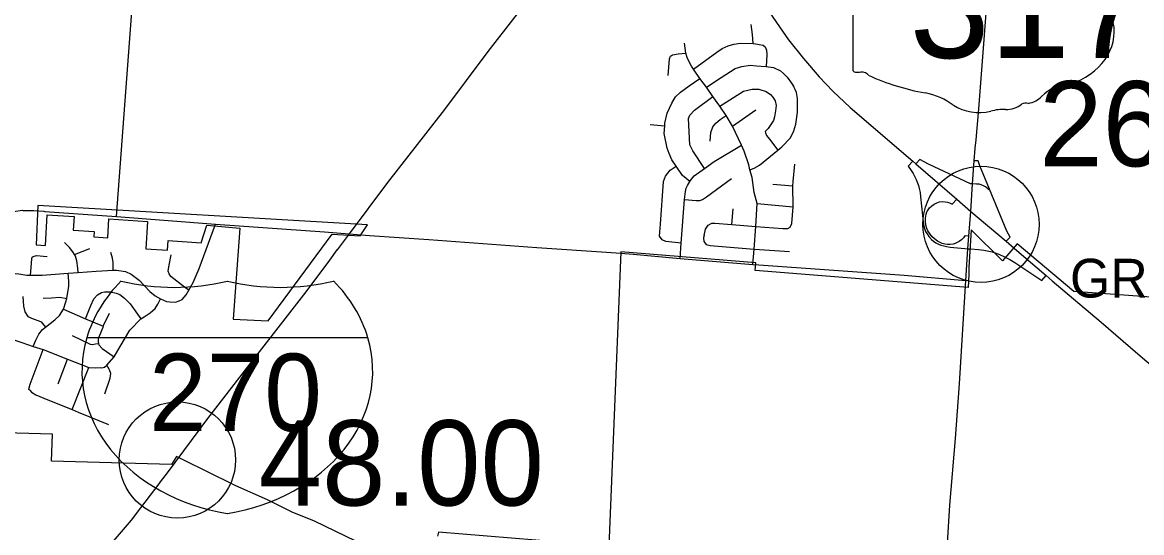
# Model space of a CAD drawing. Extents: x 1729596 to 1934326, y 644115 to 911751.
# Drawn here: x 1848780 to 1863218, y 684257 to 690843 of the extents above; entities that cross this region are included whole.
import ezdxf

# ---------------------------------------------------------------- set-up
doc = ezdxf.new("R2010")
doc.units = 0
for name, color, linetype in [('Default', 7, 'Continuous'), ('GM_X_City_Street', 7, 'Continuous'), ('GM_X_Corporation', 7, 'Continuous'), ('GM_X_Corporation_Text', 7, 'Continuous'), ('GM_X_County_Road', 7, 'Continuous'), ('GM_X_Interchange_Ramps', 7, 'Continuous'), ('GM_X_Interstate_Route', 7, 'Continuous'), ('GM_X_Interstate_Shield', 7, 'Continuous'), ('GM_X_State_Route', 7, 'Continuous'), ('GM_X_State_Shield', 7, 'Continuous'), ('GM_X_US_Route', 7, 'Continuous')]:
    doc.layers.add(name, color=color, linetype=linetype)

msp = doc.modelspace()

# ---------------------------------------------------------------- linework, layer by layer
at = {"layer": 'Default'}
for centre in [(1861146, 688236), (1850780, 685195)]:
    msp.add_circle(centre, 750, dxfattribs=at)
at = {"layer": 'GM_X_City_Street'}
for points in [[(1849993, 688339), (1850200, 691096), (1850245, 691692), (1850400, 693755)], [(1858206, 690570), (1858197, 690688), (1858181, 690816)], [(1858203, 687718), (1858220, 687916), (1858243, 688207), (1858260, 688504), (1858218, 688646), (1858192, 688840), (1858165, 688941), (1858149, 689003), (1858090, 689179), (1858055, 689260), (1857940, 689505), (1857859, 689641), (1857776, 689762), (1857687, 689888), (1857603, 690006), (1857519, 690120), (1857439, 690237), (1857411, 690278), (1857358, 690378), (1857340, 690447), (1857321, 690573)], [(1857439, 690237), (1857737, 690458), (1857805, 690506), (1857883, 690538), (1857959, 690561), (1858045, 690573), (1858206, 690570), (1858212, 690569), (1858334, 690548), (1858360, 690528), (1858380, 690484), (1858382, 690426), (1858379, 690345), (1858375, 690275)], [(1857110, 690157), (1857129, 690373), (1857141, 690407), (1857167, 690422), (1857240, 690436), (1857340, 690447)], [(1857603, 690006), (1857796, 690131), (1857974, 690246), (1858062, 690272), (1858168, 690289), (1858251, 690281), (1858375, 690275), (1858471, 690261), (1858558, 690218), (1858600, 690182), (1858644, 690134), (1858701, 690060), (1858733, 690010)], [(1857388, 688788), (1857294, 688867), (1857212, 688986), (1857158, 689067), (1857124, 689149), (1857099, 689219), (1857057, 689408), (1857066, 689509), (1857068, 689541), (1857098, 689671), (1857158, 689802), (1857207, 689880), (1857269, 689941), (1857383, 690023), (1857519, 690120)], [(1858165, 688941), (1858219, 688961), (1858289, 689001), (1858523, 689193), (1858577, 689237), (1858689, 689353), (1858733, 689442), (1858759, 689530), (1858778, 689685), (1858780, 689859), (1858765, 689937), (1858747, 689978), (1858733, 690010)], [(1857577, 688958), (1857428, 689185), (1857390, 689264), (1857371, 689600), (1857391, 689644), (1857451, 689708), (1857687, 689888)], [(1857776, 689762), (1858083, 689955), (1858194, 689982), (1858280, 689980), (1858376, 689952), (1858430, 689912), (1858461, 689878)], [(1858461, 689878), (1858489, 689832), (1858503, 689772), (1858495, 689700), (1858482, 689622), (1858468, 689577), (1858436, 689523), (1858400, 689475), (1858362, 689433), (1858364, 689417), (1858380, 689383), (1858419, 689335), (1858523, 689193)], [(1857940, 689505), (1858243, 689715)], [(1857651, 689308), (1857660, 689420), (1857688, 689493), (1857724, 689541), (1857782, 689589), (1857859, 689641)], [(1856878, 689524), (1857066, 689509)], [(1857267, 687797), (1857279, 687994), (1857320, 688555), (1857333, 688661), (1857343, 688701), (1857358, 688737), (1857388, 688788), (1857411, 688820), (1857447, 688863), (1857577, 688958), (1857704, 689045), (1858055, 689260)], [(1857279, 687994), (1857080, 688013), (1857033, 688035), (1856999, 688083), (1857010, 688238), (1857048, 688791), (1857074, 688856), (1857135, 688935), (1857212, 688986)], [(1858723, 688784), (1858723, 688787), (1858743, 689011)], [(1857320, 688555), (1857473, 688545), (1857517, 688544), (1857553, 688555), (1857604, 688589), (1857927, 688829)], [(1858461, 688755), (1858718, 688732)], [(1858653, 688181), (1858685, 688198), (1858706, 688245), (1858721, 688463), (1858718, 688732), (1858723, 688784)], [(1848804, 688416), (1848895, 688414), (1848911, 688413)], [(1857931, 688236), (1857948, 688434)], [(1858260, 688504), (1858721, 688463)], [(1850757, 687232), (1850803, 687248), (1850839, 687266), (1850893, 687326), (1850925, 687385), (1850981, 687485), (1851060, 687664), (1851182, 687991), (1851271, 688239)], [(1857575, 688092), (1857592, 688175), (1857626, 688224), (1857674, 688251), (1857713, 688251), (1857931, 688236), (1858243, 688207), (1858590, 688183), (1858653, 688181)], [(1849500, 687613), (1849494, 687671), (1849484, 687763), (1849464, 687825), (1849453, 687845), (1849431, 687883), (1849389, 687937), (1849323, 688001)], [(1853256, 688094), (1854025, 688040), (1855415, 687939), (1856313, 687875), (1856498, 687863), (1856659, 687849)], [(1857575, 688092), (1857568, 688060), (1857572, 688013), (1857600, 687977), (1857651, 687962), (1858220, 687916), (1858225, 687915)], [(1848885, 687579), (1848893, 687679), (1848900, 687789), (1848908, 687811), (1848920, 687819), (1848960, 687833), (1849101, 687822)], [(1849453, 687845), (1849648, 687924)], [(1849952, 687644), (1849951, 687742), (1849941, 687801), (1849919, 687871)], [(1850925, 687385), (1850871, 687425), (1850694, 687564), (1850674, 687596), (1850659, 687630), (1850667, 687687), (1850701, 687841)], [(1856659, 687849), (1857267, 687797), (1858203, 687718), (1858280, 687713)], [(1858225, 687915), (1858677, 687884)], [(1858280, 687713), (1860155, 687580), (1860950, 687512)], [(1848549, 687615), (1848736, 687596), (1848837, 687578), (1848885, 687579), (1849035, 687579), (1849370, 687604), (1849434, 687608), (1849500, 687613), (1849731, 687631), (1849952, 687644), (1849992, 687646), (1850110, 687627), (1850184, 687591), (1850285, 687517), (1850353, 687443), (1850422, 687371), (1850492, 687315), (1850562, 687273), (1850639, 687239), (1850682, 687235), (1850757, 687232)], [(1848921, 686661), (1848954, 686742), (1848994, 686817), (1849038, 686879), (1849077, 686909), (1849200, 687002), (1849258, 687060), (1849309, 687140), (1849341, 687235), (1849352, 687277), (1849377, 687436), (1849379, 687500), (1849370, 687604)], [(1848786, 687303), (1848796, 687179), (1848812, 687107), (1848851, 687045), (1848917, 687015), (1848991, 686989), (1849021, 686977), (1849040, 686955), (1849077, 686909)], [(1849046, 687282), (1849157, 687289), (1849261, 687295), (1849352, 687277)], [(1849593, 687018), (1849664, 687190), (1849702, 687274), (1849748, 687327), (1849802, 687357), (1849840, 687365), (1849916, 687363), (1849991, 687349), (1850039, 687332), (1850095, 687284), (1850172, 687210), (1850308, 687016)], [(1849785, 686388), (1849803, 686386), (1849838, 686394), (1849868, 686417), (1849964, 686525), (1850043, 686660), (1850167, 686871), (1850308, 687016), (1850349, 687044), (1850427, 687094), (1850493, 687150), (1850529, 687205), (1850562, 687273)], [(1849309, 687140), (1849593, 687018), (1849792, 686934), (1849820, 686920), (1849818, 686904), (1849806, 686875), (1849758, 686757), (1849756, 686721), (1849761, 686699), (1849766, 686679), (1849811, 686633), (1849964, 686525)], [(1849820, 686920), (1849905, 687088)], [(1848495, 686930), (1848488, 686861), (1848527, 686815), (1848593, 686773), (1848774, 686709), (1848921, 686661), (1849048, 686621), (1849361, 686494), (1849636, 686390), (1849721, 686386), (1849785, 686388)], [(1849423, 686800), (1849654, 686690), (1849684, 686687), (1849724, 686695), (1849761, 686699)], [(1848876, 686096), (1848864, 686106), (1848868, 686126), (1848882, 686173), (1849048, 686621)], [(1849241, 686176), (1849361, 686494)], [(1849423, 685844), (1849636, 686390)], [(1849843, 686047), (1849914, 686252), (1849920, 686312), (1849902, 686356), (1849868, 686417)], [(1848876, 686096), (1848896, 686072), (1848954, 686034), (1849109, 685971), (1849423, 685844), (1849498, 685813), (1849499, 685813)], [(1849499, 685813), (1849892, 685654)]]:
    msp.add_lwpolyline(points, dxfattribs=at)
at = {"layer": 'GM_X_Corporation'}
msp.add_lwpolyline([(1848956, 687970), (1849079, 687964), (1849099, 688358), (1849447, 688336), (1849436, 688161), (1849705, 688143), (1849701, 688074), (1849880, 688062), (1849896, 688306), (1850395, 688274), (1850372, 687920), (1850651, 687902), (1850659, 688026), (1851084, 687999), (1851161, 688227), (1851585, 688186), (1851500, 687011), (1851949, 686990), (1852778, 688109), (1853137, 688086), (1853231, 688228), (1848979, 688481)], close=True, dxfattribs=at)
for points in [[(1863635, 687276), (1862344, 687368), (1861611, 687984), (1861425, 687763), (1861021, 688163), (1860987, 687679), (1860987, 687588), (1860981, 687422), (1858232, 687641), (1858240, 687741), (1856501, 687880), (1856343, 684081), (1854149, 684264), (1854136, 684210)], [(1853083, 684145), (1852547, 684407), (1852261, 684521), (1851942, 684681), (1851532, 684863), (1851133, 685057), (1850904, 685171), (1850768, 685239), (1850703, 685135), (1849157, 685178), (1849167, 685528), (1847937, 685563)]]:
    msp.add_lwpolyline(points, dxfattribs=at)
at = {"layer": 'GM_X_County_Road'}
for points in [[(1848593, 688392), (1848595, 688393), (1848668, 688402), (1848779, 688417), (1848789, 688416), (1848804, 688416)], [(1848911, 688413), (1848927, 688413), (1849055, 688404), (1849070, 688403)], [(1849070, 688403), (1849993, 688339), (1851271, 688239), (1852679, 688139), (1852994, 688113), (1853256, 688094), (1853256, 688094)]]:
    msp.add_lwpolyline(points, dxfattribs=at)
at = {"layer": 'GM_X_Interchange_Ramps'}
for points in [[(1860265, 689050), (1860207, 688985), (1860247, 688929), (1860271, 688891), (1860294, 688849), (1860310, 688815), (1860324, 688779), (1860338, 688738), (1860349, 688699), (1860360, 688646), (1860366, 688593), (1860404, 688229), (1860417, 688181), (1860432, 688145), (1860450, 688113), (1860475, 688077), (1860507, 688042), (1860533, 688020), (1860565, 687998), (1860598, 687980), (1860627, 687968), (1860665, 687957), (1860700, 687951), (1860747, 687943), (1860938, 687925), (1860978, 687922)], [(1861038, 688759), (1861010, 688760), (1860467, 689011), (1860355, 689074), (1860305, 689015)], [(1861471, 688017), (1861520, 688071), (1861478, 688150), (1861257, 688688), (1861132, 688992), (1861109, 689054), (1861058, 689057)], [(1861257, 688688), (1861245, 688683), (1861226, 688703), (1861204, 688721), (1861179, 688735), (1861150, 688747), (1861124, 688753), (1861105, 688755), (1861086, 688756), (1861038, 688759)], [(1860991, 688085), (1860937, 688089), (1860918, 688063), (1860893, 688037), (1860866, 688016), (1860838, 688000), (1860812, 687989), (1860786, 687981), (1860750, 687975), (1860715, 687974), (1860681, 687978), (1860644, 687988), (1860585, 688020), (1860545, 688048), (1860511, 688080), (1860480, 688120), (1860461, 688153), (1860448, 688184), (1860435, 688227), (1860428, 688271), (1860428, 688317), (1860437, 688366), (1860449, 688396), (1860463, 688423), (1860481, 688447), (1860511, 688477), (1860541, 688498), (1860577, 688515), (1860611, 688525), (1860645, 688529), (1860684, 688528), (1860715, 688522), (1860741, 688514), (1860776, 688498), (1860836, 688560)], [(1860978, 687922), (1861013, 687919), (1861112, 687912), (1861146, 687909), (1861184, 687903), (1861291, 687879), (1861374, 687852), (1861450, 687818), (1861516, 687784), (1861583, 687744), (1861930, 687513), (1861985, 687576)]]:
    msp.add_lwpolyline(points, dxfattribs=at)
at = {"layer": 'GM_X_Interstate_Route'}
for points in [[(1855721, 691691), (1855482, 691365), (1854785, 690465), (1854227, 689720), (1853491, 688775), (1852994, 688113)], [(1852994, 688113), (1852840, 687906), (1852838, 687905)], [(1852838, 687905), (1852741, 687774), (1852437, 687366), (1851683, 686397), (1851166, 685731), (1850647, 685030), (1850558, 684912), (1850538, 684886)], [(1850538, 684886), (1850248, 684503), (1850224, 684472)], [(1850224, 684472), (1850183, 684418), (1849646, 683789), (1849356, 683495), (1849183, 683330), (1849173, 683321)]]:
    msp.add_lwpolyline(points, dxfattribs=at)
at = {"layer": 'GM_X_Interstate_Shield'}
msp.add_line((1853236, 686770), (1849610, 686770), dxfattribs=at)
msp.add_line((1853236, 686770), (1849610, 686770), dxfattribs=at)
for centre, start_param, end_param in [((1851892, 686342), 2.47259, 2.911027), ((1850739, 689298), 4.415841, 5.008937), ((1852108, 689298), 4.415841, 5.008937), ((1850955, 686342), 0.230566, 0.669003), ((1851892, 686342), 2.911027, 4.511031), ((1850955, 686342), 4.913747, 6.513751)]:
    msp.add_ellipse(centre, major_axis=(2344, 0), ratio=0.8, start_param=start_param, end_param=end_param, dxfattribs=at)
at = {"layer": 'GM_X_State_Route'}
for points in [[(1861082, 689327), (1861118, 689728), (1861270, 691692), (1861312, 692190), (1861342, 692610)], [(1861072, 689219), (1861082, 689327)], [(1861015, 688403), (1861038, 688759), (1861058, 689057), (1861072, 689219)], [(1860982, 687976), (1860991, 688085), (1861015, 688403)], [(1860950, 687512), (1860978, 687922), (1860982, 687976)], [(1860712, 684123), (1860745, 684612), (1860816, 685471), (1860868, 686179), (1860950, 687512)]]:
    msp.add_lwpolyline(points, dxfattribs=at)
at = {"layer": 'GM_X_State_Shield'}
msp.add_line((1859493, 692347), (1859493, 690234), dxfattribs=at)
for centre, major_axis, start_param, end_param in [((1861941, 690727), (923, 0), 5.101752, 6.440018), ((1859534, 690230), (40.7, 0), 3.00124, 4.508301), ((1859540, 690446), (310, 0), 4.665946, 4.897461), ((1859603, 690112), (112, 0), 0.519207, 1.627899), ((1861017, 692011), (2665, 0), 4.195997, 4.488961), ((1862330, 689641), (506, 0), 1.647645, 2.488434), ((1860222, 689285), (834, 0), 0.823519, 1.323587), ((1861689, 690029), (298, 0), 4.937069, 5.64225), ((1861124, 690102), (529, 0), 4.026481, 4.996735), ((1861430, 689371), (435, 0), 1.495662, 1.94098), ((1861468, 689943), (282, 0), 4.691044, 5.507374), ((1861723, 689739), (79.4, 0), 1.147584, 2.315152)]:
    msp.add_ellipse(centre, major_axis=major_axis, ratio=0.8, start_param=start_param, end_param=end_param, dxfattribs=at)
at = {"layer": 'GM_X_US_Route'}
for points in [[(1856652, 693074), (1856737, 693020), (1856777, 692989), (1856897, 692893), (1857063, 692753), (1857202, 692621), (1857327, 692490), (1857455, 692349), (1857598, 692163), (1857712, 692012), (1858010, 691573), (1858344, 691078), (1858661, 690619), (1858855, 690377), (1859060, 690138), (1859236, 689954), (1859458, 689742), (1860265, 689050), (1860305, 689015), (1860836, 688560), (1861015, 688403)], [(1861015, 688403), (1861471, 688017), (1861608, 687899)], [(1861608, 687899), (1861985, 687576), (1862065, 687507)], [(1862065, 687507), (1862694, 686973), (1863169, 686564), (1863517, 686267)]]:
    msp.add_lwpolyline(points, dxfattribs=at)

# ---------------------------------------------------------------- texts
at = {"layer": 'Default'}
for s, p in [('26.00', (1861896, 688985)), ('48.00', (1851827, 684607))]:
    msp.add_text(s, height=1100, dxfattribs=at).set_placement(p)
at = {"layer": 'GM_X_Corporation_Text'}
msp.add_text('GROVEPORT', height=500, rotation=0, dxfattribs=at).set_placement((1862294, 687291))
at = {"layer": 'GM_X_Interstate_Shield'}
msp.add_text('270', height=1000, dxfattribs=at).set_placement((1850413, 685567))
at = {"layer": 'GM_X_State_Shield'}
msp.add_text('317', height=1392.2, dxfattribs=at).set_placement((1860223, 690383))

doc.saveas('drawing.dxf')
